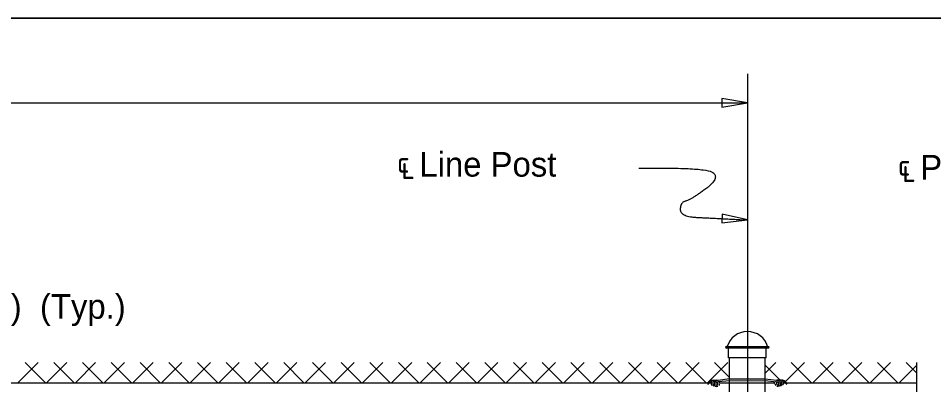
# Model space of a CAD drawing. Extents: x 0 to 41.2, y 0 to 26.
# Drawn here: x 16.23 to 23.73, y 22.96 to 25.96 of the extents above; entities that cross this region are included whole.
import ezdxf

# ---------------------------------------------------------------- set-up
doc = ezdxf.new("R2010")
doc.units = 0
for name, color, linetype in [('ActivePts-ConstElements', 7, 'Continuous'), ('CL_Major', 7, 'Continuous'), ('Dimension', 7, 'Continuous'), ('Miscellaneous', 7, 'Continuous'), ('Miscellaneous1', 7, 'Continuous'), ('SteelMisc', 7, 'Continuous'), ('SteelMisc_h', 7, 'Continuous'), ('TextStructures', 7, 'Continuous')]:
    doc.layers.add(name, color=color, linetype=linetype)

msp = doc.modelspace()

# ---------------------------------------------------------------- linework, layer by layer
at = {"layer": 'ActivePts-ConstElements'}
msp.add_lwpolyline([(0, 0), (41.2106, 0), (41.2106, 25.96), (0, 25.96)], close=True, dxfattribs=at)
at = {"layer": 'CL_Major'}
msp.add_line((22.2062, 25.5043), (22.2062, 14.6639), dxfattribs=at)
at = {"layer": 'Dimension'}
msp.add_line((2.2062, 25.2672), (22.2062, 25.2672), dxfattribs=at)
for points in [[(22.2062, 25.2672), (21.998, 25.3025), (21.998, 25.2319)], [(22.2062, 24.3062), (22.0002, 24.3528), (21.9964, 24.2823)]]:
    msp.add_lwpolyline(points, close=True, dxfattribs=at)
msp.add_lwpolyline([(23.5932, 23.1382), (23.5932, 21.1819), (23.6966, 21.1819), (23.5932, 21.1369), (23.4899, 21.0919), (23.5932, 21.0919), (23.5932, 20.1983)], dxfattribs=at)
msp.add_open_spline([(21.3167, 24.7299), (21.8625, 24.7397), (21.9849, 24.6508), (21.7407, 24.4695), (21.6558, 24.4512), (21.6558, 24.3333), (21.9339, 24.321), (22.2062, 24.3061)], degree=2, dxfattribs=at)
at = {"layer": 'Miscellaneous'}
for p, q in [((16.2217, 22.9695), (16.3884, 23.1361)), ((16.281, 23.1361), (16.4476, 22.9695)), ((16.4575, 22.9695), (16.6241, 23.1361)), ((16.5167, 23.1361), (16.6833, 22.9695)), ((16.6932, 22.9695), (16.8598, 23.1361)), ((16.7524, 23.1361), (16.919, 22.9695)), ((16.9289, 22.9695), (17.0955, 23.1361)), ((16.9881, 23.1361), (17.1547, 22.9695)), ((17.1646, 22.9695), (17.3312, 23.1361)), ((17.2238, 23.1361), (17.3904, 22.9695)), ((17.4003, 22.9695), (17.5669, 23.1361)), ((17.4595, 23.1361), (17.6262, 22.9695)), ((17.636, 22.9695), (17.8026, 23.1361)), ((17.6952, 23.1361), (17.8619, 22.9695)), ((17.8717, 22.9695), (18.0383, 23.1361)), ((17.9309, 23.1361), (18.0976, 22.9695)), ((18.1074, 22.9695), (18.274, 23.1361)), ((18.1666, 23.1361), (18.3333, 22.9695)), ((18.3431, 22.9695), (18.5097, 23.1361)), ((18.4023, 23.1361), (18.569, 22.9695)), ((18.5788, 22.9695), (18.7454, 23.1361)), ((18.638, 23.1361), (18.8047, 22.9695)), ((18.8145, 22.9695), (18.9811, 23.1361)), ((18.8737, 23.1361), (19.0404, 22.9695)), ((19.0502, 22.9695), (19.2168, 23.1361)), ((19.1094, 23.1361), (19.2761, 22.9695)), ((19.2859, 22.9695), (19.4525, 23.1361)), ((19.3451, 23.1361), (19.5118, 22.9695)), ((19.5216, 22.9695), (19.6882, 23.1361)), ((19.5808, 23.1361), (19.7475, 22.9695)), ((19.7573, 22.9695), (19.9239, 23.1361)), ((19.8165, 23.1361), (19.9832, 22.9695)), ((19.993, 22.9695), (20.1597, 23.1361)), ((20.0522, 23.1361), (20.2189, 22.9695)), ((20.2287, 22.9695), (20.3954, 23.1361)), ((20.2879, 23.1361), (20.4546, 22.9695)), ((20.4644, 22.9695), (20.6311, 23.1361)), ((20.5236, 23.1361), (20.6903, 22.9695)), ((20.7001, 22.9695), (20.8668, 23.1361)), ((20.7593, 23.1361), (20.926, 22.9695)), ((20.9358, 22.9695), (21.1025, 23.1361)), ((20.995, 23.1361), (21.1617, 22.9695)), ((21.1715, 22.9695), (21.3382, 23.1361)), ((21.2307, 23.1361), (21.3974, 22.9695)), ((21.4072, 22.9695), (21.5739, 23.1361)), ((21.4664, 23.1361), (21.6331, 22.9695)), ((21.6429, 22.9695), (21.8096, 23.1361)), ((21.7021, 23.1361), (21.8688, 22.9695)), ((21.8786, 22.9695), (22.0453, 23.1361)), ((21.9378, 23.1361), (22.0604, 23.0136)), ((22.3521, 23.0495), (22.4386, 23.1361)), ((22.5192, 22.981), (22.6743, 23.1361)), ((22.5669, 23.1361), (22.7336, 22.9695)), ((22.7434, 22.9695), (22.91, 23.1361)), ((22.8026, 23.1361), (22.9693, 22.9695)), ((22.9791, 22.9695), (23.1458, 23.1361)), ((23.0383, 23.1361), (23.205, 22.9695)), ((23.2148, 22.9695), (23.3815, 23.1361)), ((23.274, 23.1361), (23.4407, 22.9695)), ((23.5097, 23.1361), (23.5931, 23.0527)), ((22.3521, 23.1153), (22.4743, 22.993)), ((23.4505, 22.9695), (23.5931, 23.1121)), ((22.5077, 22.9695), (22.5121, 22.9739))]:
    msp.add_line(p, q, dxfattribs=at)
at = {"layer": 'Miscellaneous1'}
msp.add_lwpolyline([(0, 25.96), (41.2106, 25.96), (41.2106, 0), (0, 0)], close=True, dxfattribs=at)
at = {"layer": 'SteelMisc'}
for p, q in [((22.034, 23.2681), (22.3785, 23.2681)), ((22.3785, 23.2559), (22.034, 23.2559)), ((22.0522, 23.1761), (22.0522, 23.2559)), ((22.3603, 23.1761), (22.3603, 23.2559)), ((22.3603, 23.1761), (22.0522, 23.1761)), ((22.0604, 17.5309), (22.0604, 23.1761)), ((22.3521, 17.5309), (22.3521, 23.1761)), ((22.0604, 23.0021), (21.9655, 22.991)), ((22.0604, 22.9876), (21.9678, 22.978)), ((22.0604, 23.0021), (22.3516, 23.0038)), ((22.0604, 22.9876), (22.3516, 22.9892)), ((22.3516, 23.0038), (22.4459, 22.9926)), ((22.3516, 22.9892), (22.4437, 22.9798)), ((13.4503, 22.9695), (21.8852, 22.9695)), ((21.8952, 22.9695), (21.9083, 22.9695)), ((21.9782, 22.9695), (22.0604, 22.9695)), ((22.3521, 22.9695), (22.4325, 22.9695)), ((22.5028, 22.9695), (22.518, 22.9695)), ((22.5265, 22.9695), (23.5931, 22.9695))]:
    msp.add_line(p, q, dxfattribs=at)
for centre, start, end in [((22.034, 23.2618), 91.1647, 268.8353), ((22.3784, 23.2618), 271.1647, 88.8353)]:
    msp.add_arc(centre, 0.00613, start, end, dxfattribs=at)
for centre, major_axis, ratio, start_param, end_param in [((22.2069, 23.227), (0.1711, 0), 0.957868, 0.252602, 2.888574), ((21.9195, 22.9552), (0.0373, 0), 0.957868, 1.486836, 3.108042), ((21.932, 22.9697), (0.023, 0), 0.957868, 1.29026, 2.970541), ((21.9507, 22.9643), (0.0295, 0), 0.957868, 1.220941, 4.039556), ((21.9642, 22.9661), (-0.0303, -0.0108), 0.724765, 4.35367, 6.324556), ((22.4573, 22.966), (-0.0251, 0), 0.957868, 5.673972, 5.875498), ((22.4418, 22.9549), (0.0259, 0), 0.957868, 0.655696, 1.505671), ((22.4468, 22.9678), (0.0303, -0.0108), 0.724765, 6.241815, 8.212701), ((22.4603, 22.9661), (-0.0295, 0), 0.957868, 2.243629, 5.062245), ((22.479, 22.9714), (-0.023, 0), 0.957868, 3.312645, 4.992926), ((22.4915, 22.957), (-0.0373, 0), 0.957868, 3.175144, 4.79635), ((22.4704, 22.9173), (0.0724, 0), 0.957868, 0.631079, 1.121037), ((21.9406, 22.9155), (-0.0724, 0), 0.957868, 5.162149, 5.652106), ((21.9331, 22.9671), (-0.0249, 0), 0.957868, 6.009018, 7.089857), ((21.9541, 22.9575), (0.0206, -0.0021), 0.798607, 3.333154, 5.220153), ((21.9609, 22.962), (-0.0139, 0), 0.957868, 5.22362, 6.905413), ((21.9552, 22.9596), (-0.00795, 0), 0.957868, 6.140374, 9.314262), ((21.9693, 22.9532), (-0.0259, 0), 0.957868, 4.777514, 5.62749), ((21.9535, 22.9654), (0.0119, 0), 0.957868, 5.725876, 7.416677), ((21.9535, 22.9654), (0.0119, 0), 0.957868, 5.639684, 5.723117), ((21.9535, 22.9654), (0.0119, 0), 0.957868, 5.639684, 5.723117), ((21.9538, 22.9642), (0.0251, 0), 0.957868, 5.531357, 6.227833), ((21.9538, 22.9642), (0.0251, 0), 0.957868, 0.407687, 0.609214), ((22.4573, 22.966), (-0.0251, 0), 0.957868, 0.055352, 0.751829), ((22.4575, 22.9672), (-0.0119, 0), 0.957868, 5.149694, 6.840495), ((22.4575, 22.9672), (-0.0119, 0), 0.957868, 0.560069, 0.643501), ((22.4558, 22.9614), (0.00795, 0), 0.957868, 3.252108, 6.425997), ((22.4569, 22.9592), (-0.0206, -0.0021), 0.798607, 1.063032, 2.950031), ((22.4501, 22.9638), (0.0139, 0), 0.957868, 5.660958, 7.342751), ((22.4779, 22.9689), (0.0249, 0), 0.957868, 5.476514, 6.557353)]:
    msp.add_ellipse(centre, major_axis=major_axis, ratio=ratio, start_param=start_param, end_param=end_param, dxfattribs=at)
at = {"layer": 'SteelMisc_h'}
msp.add_line((22.0604, 22.9695), (22.3521, 22.9695), dxfattribs=at)

# ---------------------------------------------------------------- texts
at = {"layer": 'TextStructures'}
for s, p in [('℄ Line Post', (19.3313, 24.6617)), ('℄ Pull Post', (23.4401, 24.6377)), ('Varies (1\'-0" Max.)  (Typ.)', (14.0385, 23.4963))]:
    msp.add_text(s, height=0.2016, dxfattribs=at).set_placement(p)

doc.saveas('drawing.dxf')
